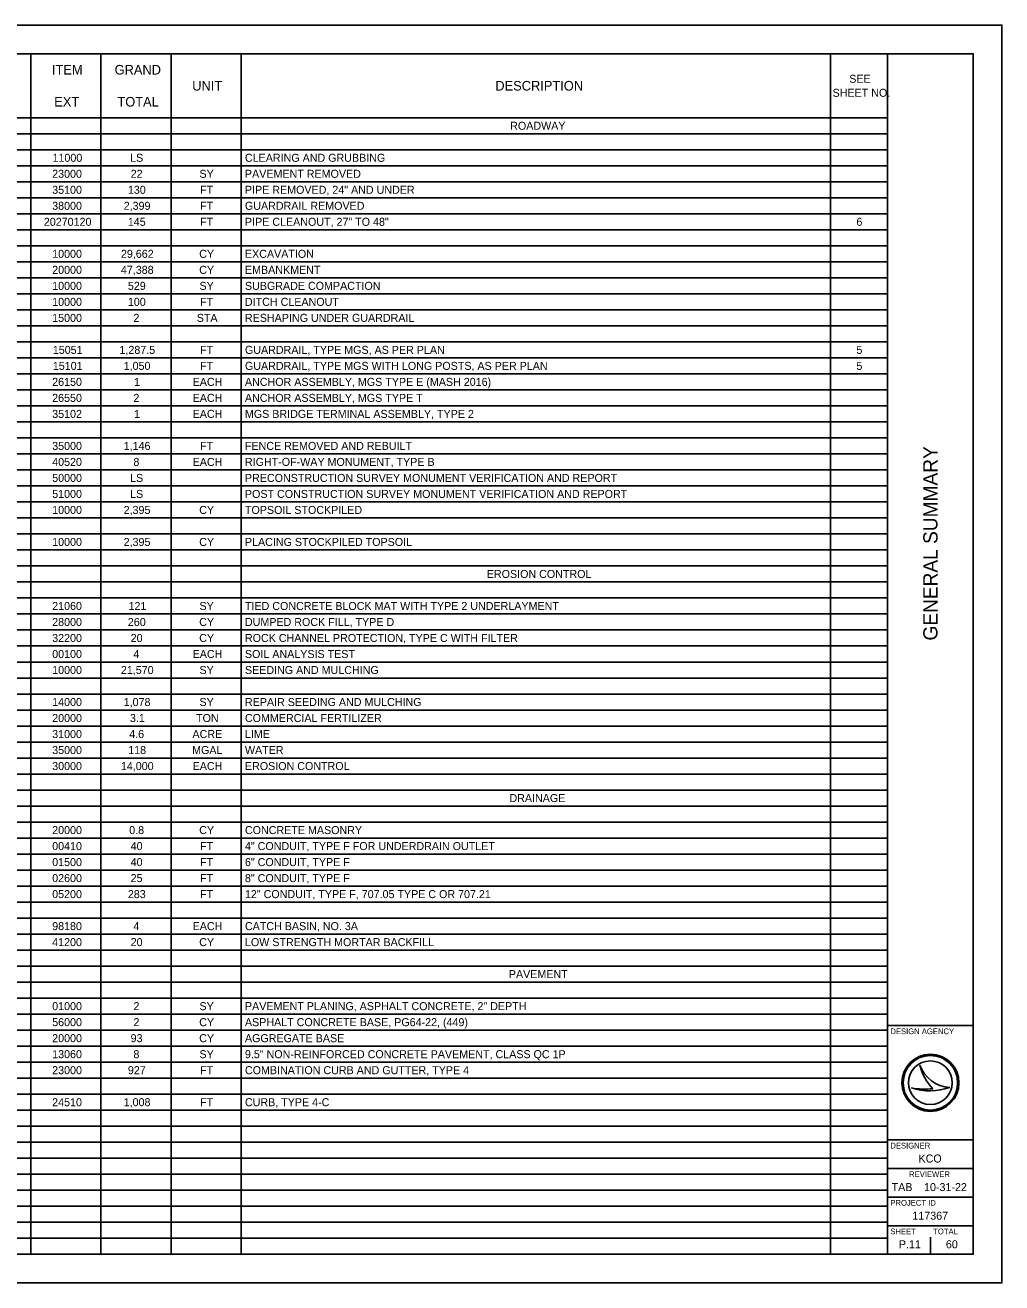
# Model space of a CAD drawing. Extents: x 0 to 34, y 0 to 22.
# Drawn here: x 16.91 to 34, y 0 to 22 of the extents above; entities that cross this region are included whole.
import ezdxf

# ---------------------------------------------------------------- set-up
doc = ezdxf.new("R2010")
doc.units = 0
for name, color, linetype in [('Default', 7, 'Continuous'), ('SH_Border', 7, 'Continuous'), ('SH_Cut_Line', 7, 'Continuous'), ('SH_Data', 7, 'Continuous')]:
    doc.layers.add(name, color=color, linetype=linetype)

msp = doc.modelspace()

# ---------------------------------------------------------------- linework, layer by layer
at = {"layer": 'Default'}
for p, q in [((1.5, 21.5), (32, 21.5)), ((17.012, 21.5), (17.012, 0.5)), ((18.239, 21.5), (18.239, 0.5)), ((19.466, 21.5), (19.466, 0.5)), ((20.693, 21.5), (20.693, 0.5)), ((31.002, 21.5), (31.002, 0.5)), ((32, 21.5), (32, 0.5)), ((1.5, 20.38), (32, 20.38)), ((1.5, 20.1), (32, 20.1)), ((1.5, 19.82), (32, 19.82)), ((1.5, 19.54), (32, 19.54)), ((1.5, 19.26), (32, 19.26)), ((1.5, 18.98), (32, 18.98)), ((1.5, 18.7), (32, 18.7)), ((1.5, 18.42), (32, 18.42)), ((1.5, 18.14), (32, 18.14)), ((1.5, 17.86), (32, 17.86)), ((1.5, 17.58), (32, 17.58)), ((1.5, 17.3), (32, 17.3)), ((1.5, 17.02), (32, 17.02)), ((1.5, 16.74), (32, 16.74)), ((1.5, 16.46), (32, 16.46)), ((1.5, 16.18), (32, 16.18)), ((1.5, 15.9), (32, 15.9)), ((1.5, 15.62), (32, 15.62)), ((1.5, 15.34), (32, 15.34)), ((1.5, 15.06), (32, 15.06)), ((1.5, 14.78), (32, 14.78)), ((1.5, 14.5), (32, 14.5)), ((1.5, 14.22), (32, 14.22)), ((1.5, 13.94), (32, 13.94)), ((1.5, 13.66), (32, 13.66)), ((1.5, 13.38), (32, 13.38)), ((1.5, 13.1), (32, 13.1)), ((1.5, 12.82), (32, 12.82)), ((1.5, 12.54), (32, 12.54)), ((1.5, 12.26), (32, 12.26)), ((1.5, 11.98), (32, 11.98)), ((1.5, 11.7), (32, 11.7)), ((1.5, 11.42), (32, 11.42)), ((1.5, 11.14), (32, 11.14)), ((1.5, 10.86), (32, 10.86)), ((1.5, 10.58), (32, 10.58)), ((1.5, 10.3), (32, 10.3)), ((1.5, 10.02), (32, 10.02)), ((1.5, 9.74), (32, 9.74)), ((1.5, 9.46), (32, 9.46)), ((1.5, 9.18), (32, 9.18)), ((1.5, 8.9), (32, 8.9)), ((1.5, 8.62), (32, 8.62)), ((1.5, 8.34), (32, 8.34)), ((1.5, 8.06), (32, 8.06)), ((1.5, 7.78), (32, 7.78)), ((1.5, 7.5), (32, 7.5)), ((1.5, 7.22), (32, 7.22)), ((1.5, 6.94), (32, 6.94)), ((1.5, 6.66), (32, 6.66)), ((1.5, 6.38), (32, 6.38)), ((1.5, 6.1), (32, 6.1)), ((1.5, 5.82), (32, 5.82)), ((1.5, 5.54), (32, 5.54)), ((1.5, 5.26), (32, 5.26)), ((1.5, 4.98), (32, 4.98)), ((1.5, 4.7), (32, 4.7)), ((1.5, 4.42), (32, 4.42)), ((1.5, 4.14), (32, 4.14)), ((1.5, 3.86), (32, 3.86)), ((1.5, 3.58), (32, 3.58)), ((1.5, 3.3), (32, 3.3)), ((1.5, 3.02), (32, 3.02)), ((1.5, 2.74), (32, 2.74)), ((1.5, 2.46), (32, 2.46)), ((1.5, 2.18), (32, 2.18)), ((1.5, 1.9), (32, 1.9)), ((1.5, 1.62), (32, 1.62)), ((1.5, 1.34), (32, 1.34)), ((1.5, 1.06), (32, 1.06)), ((1.5, 0.78), (32, 0.78)), ((1.5, 0.5), (32, 0.5))]:
    msp.add_line(p, q, dxfattribs=at)
at = {"layer": 'SH_Border'}
for p, q in [((32, 0.5), (32, 21.5)), ((32, 4.5), (33.5, 4.5)), ((32, 2.5), (33.5, 2.5)), ((32, 2), (33.5, 2)), ((32, 1.5), (33.5, 1.5)), ((32, 1), (33.5, 1))]:
    msp.add_line(p, q, dxfattribs=at)
msp.add_lwpolyline([(1.5, 21.5), (33.5, 21.5), (33.5, 0.5), (1.5, 0.5)], close=True, dxfattribs=at)
at = {"layer": 'SH_Cut_Line'}
msp.add_lwpolyline([(0, 0), (34, 0), (34, 22), (0, 22)], close=True, dxfattribs=at)
at = {"layer": 'SH_Data'}
for p, q in [((32.567, 3.81), (32.567, 3.81)), ((32.417, 3.41), (32.417, 3.41)), ((32.75, 3.5), (32.75, 3.5)), ((33.087, 3.419), (33.087, 3.419)), ((32.375, 0.675), (32.375, 0.675)), ((32.75, 0.5), (32.75, 0.8))]:
    msp.add_line(p, q, dxfattribs=at)
for radius in [0.5, 0.477, 0.477, 0.382]:
    msp.add_circle((32.75, 3.5), radius, dxfattribs=at)
for centre, radius, start, end in [((33.116, 3.998), 0.58, 198.9257, 198.9319), ((33.347, 3.97), 0.796, 191.6379, 191.6421), ((33.116, 3.998), 0.58, 198.9319, 267.1657), ((33.347, 3.97), 0.796, 191.6421, 226.0947), ((32.739, 4.37), 1.013, 251.4576, 290.0832), ((32.648, 4.654), 1.266, 259.4964, 259.4995), ((32.739, 4.37), 1.013, 251.4527, 251.4576), ((32.648, 4.654), 1.266, 259.4995, 276.6672)]:
    msp.add_arc(centre, radius, start, end, dxfattribs=at)

# ---------------------------------------------------------------- texts
at = {"layer": 'Default'}
for s, height, p in [('ITEM', 0.168, (17.383, 21.136)), ('GRAND', 0.168, (18.479, 21.136)), ('SEE ', 0.14, (31.331, 20.992)), ('UNIT', 0.168, (19.837, 20.856)), ('DESCRIPTION', 0.168, (25.139, 20.856)), ('EXT', 0.168, (17.423, 20.576)), ('TOTAL', 0.168, (18.528, 20.576)), ('SHEET NO.', 0.14, (31.039, 20.747)), ('ROADWAY', 0.14, (25.399, 20.17)), ('11000', 0.14, (17.393, 19.61)), ('LS', 0.14, (18.75, 19.61)), ('CLEARING AND GRUBBING', 0.14, (20.759, 19.61)), ('23000', 0.14, (17.387, 19.33)), ('22', 0.14, (18.76, 19.33)), ('SY', 0.14, (19.964, 19.33)), ('PAVEMENT REMOVED', 0.14, (20.759, 19.33)), ('35100', 0.14, (17.387, 19.05)), ('130', 0.14, (18.711, 19.05)), ('FT', 0.14, (19.975, 19.05)), ('PIPE REMOVED, 24" AND UNDER', 0.14, (20.759, 19.05)), ('38000', 0.14, (17.387, 18.77)), ('2,399', 0.14, (18.638, 18.77)), ('FT', 0.14, (19.975, 18.77)), ('GUARDRAIL REMOVED', 0.14, (20.759, 18.77)), ('20270120', 0.14, (17.241, 18.49)), ('145', 0.14, (18.71, 18.49)), ('FT', 0.14, (19.975, 18.49)), ('PIPE CLEANOUT, 27" TO 48"', 0.14, (20.759, 18.49)), ('6', 0.14, (31.456, 18.49)), ('10000', 0.14, (17.387, 17.93)), ('29,662', 0.14, (18.59, 17.93)), ('CY', 0.14, (19.959, 17.93)), ('EXCAVATION', 0.14, (20.759, 17.93)), ('20000', 0.14, (17.387, 17.65)), ('47,388', 0.14, (18.589, 17.65)), ('CY', 0.14, (19.959, 17.65)), ('EMBANKMENT', 0.14, (20.759, 17.65)), ('10000', 0.14, (17.387, 17.37)), ('529', 0.14, (18.711, 17.37)), ('SY', 0.14, (19.964, 17.37)), ('SUBGRADE COMPACTION', 0.14, (20.759, 17.37)), ('10000', 0.14, (17.387, 17.09)), ('100', 0.14, (18.711, 17.09)), ('FT', 0.14, (19.975, 17.09)), ('DITCH CLEANOUT', 0.14, (20.759, 17.09)), ('15000', 0.14, (17.387, 16.81)), ('2', 0.14, (18.809, 16.81)), ('STA', 0.14, (19.916, 16.81)), ('RESHAPING UNDER GUARDRAIL', 0.14, (20.759, 16.81)), ('15051', 0.14, (17.398, 16.25)), ('1,287.5', 0.14, (18.564, 16.25)), ('FT', 0.14, (19.975, 16.25)), ('GUARDRAIL, TYPE MGS, AS PER PLAN', 0.14, (20.759, 16.25)), ('5', 0.14, (31.456, 16.25)), ('15101', 0.14, (17.398, 15.97)), ('1,050', 0.14, (18.638, 15.97)), ('FT', 0.14, (19.975, 15.97)), ('GUARDRAIL, TYPE MGS WITH LONG POSTS, AS PER PLAN', 0.14, (20.759, 15.97)), ('5', 0.14, (31.456, 15.97)), ('26150', 0.14, (17.387, 15.69)), ('1', 0.14, (18.82, 15.69)), ('EACH', 0.14, (19.844, 15.69)), ('ANCHOR ASSEMBLY, MGS TYPE E (MASH 2016)', 0.14, (20.759, 15.69)), ('26550', 0.14, (17.387, 15.41)), ('2', 0.14, (18.809, 15.41)), ('EACH', 0.14, (19.844, 15.41)), ('ANCHOR ASSEMBLY, MGS TYPE T', 0.14, (20.759, 15.41)), ('35102', 0.14, (17.387, 15.13)), ('1', 0.14, (18.82, 15.13)), ('EACH', 0.14, (19.844, 15.13)), ('MGS BRIDGE TERMINAL ASSEMBLY, TYPE 2', 0.14, (20.759, 15.13)), ('35000', 0.14, (17.387, 14.57)), ('1,146', 0.14, (18.638, 14.57)), ('FT', 0.14, (19.975, 14.57)), ('FENCE REMOVED AND REBUILT', 0.14, (20.759, 14.57)), ('40520', 0.14, (17.387, 14.29)), ('8', 0.14, (18.808, 14.29)), ('EACH', 0.14, (19.844, 14.29)), ('RIGHT-OF-WAY MONUMENT, TYPE B', 0.14, (20.759, 14.29)), ('50000', 0.14, (17.387, 14.01)), ('LS', 0.14, (18.75, 14.01)), ('PRECONSTRUCTION SURVEY MONUMENT VERIFICATION AND REPORT', 0.14, (20.759, 14.01)), ('51000', 0.14, (17.387, 13.73)), ('LS', 0.14, (18.75, 13.73)), ('POST CONSTRUCTION SURVEY MONUMENT VERIFICATION AND REPORT', 0.14, (20.759, 13.73)), ('10000', 0.14, (17.387, 13.45)), ('2,395', 0.14, (18.637, 13.45)), ('CY', 0.14, (19.959, 13.45)), ('TOPSOIL STOCKPILED', 0.14, (20.759, 13.45)), ('10000', 0.14, (17.387, 12.89)), ('2,395', 0.14, (18.637, 12.89)), ('CY', 0.14, (19.959, 12.89)), ('PLACING STOCKPILED TOPSOIL', 0.14, (20.759, 12.89)), ('EROSION CONTROL', 0.14, (24.99, 12.33)), ('21060', 0.14, (17.387, 11.77)), ('121', 0.14, (18.723, 11.77)), ('SY', 0.14, (19.964, 11.77)), ('TIED CONCRETE BLOCK MAT WITH TYPE 2 UNDERLAYMENT', 0.14, (20.759, 11.77)), ('28000', 0.14, (17.387, 11.49)), ('260', 0.14, (18.711, 11.49)), ('CY', 0.14, (19.959, 11.49)), ('DUMPED ROCK FILL, TYPE D', 0.14, (20.759, 11.49)), ('32200', 0.14, (17.387, 11.21)), ('20', 0.14, (18.76, 11.21)), ('CY', 0.14, (19.959, 11.21)), ('ROCK CHANNEL PROTECTION, TYPE C WITH FILTER', 0.14, (20.759, 11.21)), ('00100', 0.14, (17.387, 10.93)), ('4', 0.14, (18.808, 10.93)), ('EACH', 0.14, (19.844, 10.93)), ('SOIL ANALYSIS TEST', 0.14, (20.759, 10.93)), ('10000', 0.14, (17.387, 10.65)), ('21,570', 0.14, (18.589, 10.65)), ('SY', 0.14, (19.964, 10.65)), ('SEEDING AND MULCHING', 0.14, (20.759, 10.65)), ('14000', 0.14, (17.387, 10.09)), ('1,078', 0.14, (18.638, 10.09)), ('SY', 0.14, (19.964, 10.09)), ('REPAIR SEEDING AND MULCHING', 0.14, (20.759, 10.09)), ('20000', 0.14, (17.387, 9.81)), ('3.1', 0.14, (18.747, 9.81)), ('TON', 0.14, (19.904, 9.81)), ('COMMERCIAL FERTILIZER', 0.14, (20.759, 9.81)), ('31000', 0.14, (17.387, 9.53)), ('4.6', 0.14, (18.735, 9.53)), ('ACRE', 0.14, (19.841, 9.53)), ('LIME', 0.14, (20.759, 9.53)), ('35000', 0.14, (17.387, 9.25)), ('118', 0.14, (18.717, 9.25)), ('MGAL', 0.14, (19.835, 9.25)), ('WATER', 0.14, (20.759, 9.25)), ('30000', 0.14, (17.387, 8.97)), ('14,000', 0.14, (18.589, 8.97)), ('EACH', 0.14, (19.844, 8.97)), ('EROSION CONTROL', 0.14, (20.759, 8.97)), ('DRAINAGE', 0.14, (25.386, 8.41)), ('20000', 0.14, (17.387, 7.85)), ('0.8', 0.14, (18.735, 7.85)), ('CY', 0.14, (19.959, 7.85)), ('CONCRETE MASONRY', 0.14, (20.759, 7.85)), ('00410', 0.14, (17.387, 7.57)), ('40', 0.14, (18.76, 7.57)), ('FT', 0.14, (19.975, 7.57)), ('4" CONDUIT, TYPE F FOR UNDERDRAIN OUTLET', 0.14, (20.759, 7.57)), ('01500', 0.14, (17.387, 7.29)), ('40', 0.14, (18.76, 7.29)), ('FT', 0.14, (19.975, 7.29)), ('6" CONDUIT, TYPE F', 0.14, (20.759, 7.29)), ('02600', 0.14, (17.387, 7.01)), ('25', 0.14, (18.759, 7.01)), ('FT', 0.14, (19.975, 7.01)), ('8" CONDUIT, TYPE F', 0.14, (20.759, 7.01)), ('05200', 0.14, (17.387, 6.73)), ('283', 0.14, (18.711, 6.73)), ('FT', 0.14, (19.975, 6.73)), ('12" CONDUIT, TYPE F, 707.05 TYPE C OR 707.21', 0.14, (20.759, 6.73)), ('98180', 0.14, (17.387, 6.17)), ('4', 0.14, (18.808, 6.17)), ('EACH', 0.14, (19.844, 6.17)), ('CATCH BASIN, NO. 3A', 0.14, (20.759, 6.17)), ('41200', 0.14, (17.387, 5.89)), ('20', 0.14, (18.76, 5.89)), ('CY', 0.14, (19.959, 5.89)), ('LOW STRENGTH MORTAR BACKFILL', 0.14, (20.759, 5.89)), ('PAVEMENT', 0.14, (25.376, 5.33)), ('01000', 0.14, (17.387, 4.77)), ('2', 0.14, (18.809, 4.77)), ('SY', 0.14, (19.964, 4.77)), ('PAVEMENT PLANING, ASPHALT CONCRETE, 2" DEPTH', 0.14, (20.759, 4.77)), ('56000', 0.14, (17.387, 4.49)), ('2', 0.14, (18.809, 4.49)), ('CY', 0.14, (19.959, 4.49)), ('ASPHALT CONCRETE BASE, PG64-22, (449)', 0.14, (20.759, 4.49)), ('20000', 0.14, (17.387, 4.21)), ('93', 0.14, (18.759, 4.21)), ('CY', 0.14, (19.959, 4.21)), ('AGGREGATE BASE', 0.14, (20.759, 4.21)), ('13060', 0.14, (17.387, 3.93)), ('8', 0.14, (18.808, 3.93)), ('SY', 0.14, (19.964, 3.93)), ('9.5" NON-REINFORCED CONCRETE PAVEMENT, CLASS QC 1P', 0.14, (20.759, 3.93)), ('23000', 0.14, (17.387, 3.65)), ('927', 0.14, (18.711, 3.65)), ('FT', 0.14, (19.975, 3.65)), ('COMBINATION CURB AND GUTTER, TYPE 4', 0.14, (20.759, 3.65)), ('24510', 0.14, (17.387, 3.09)), ('1,008', 0.14, (18.638, 3.09)), ('FT', 0.14, (19.975, 3.09)), ('CURB, TYPE 4-C', 0.14, (20.759, 3.09))]:
    msp.add_text(s, height=height, dxfattribs=at).set_placement(p)
at = {"layer": 'SH_Data'}
msp.add_text('GENERAL SUMMARY', height=0.25, rotation=90, dxfattribs=at).set_placement((32.875, 11.235))
for s, height, p in [('DESIGN AGENCY', 0.1, (32.05, 4.35)), ('DESIGNER', 0.1, (32.05, 2.35)), ('KCO', 0.14, (32.542, 2.105)), ('REVIEWER', 0.1, (32.378, 1.85)), ('TAB', 0.14, (32.072, 1.605)), ('10-31-22', 0.14, (32.639, 1.605)), ('PROJECT ID', 0.1, (32.05, 1.35)), ('117367', 0.14, (32.435, 1.105)), ('SHEET', 0.1, (32.05, 0.85)), ('TOTAL', 0.1, (32.8, 0.85)), ('P.11', 0.14, (32.199, 0.605)), ('60', 0.14, (33.021, 0.605))]:
    msp.add_text(s, height=height, dxfattribs=at).set_placement(p)

doc.saveas('drawing.dxf')
